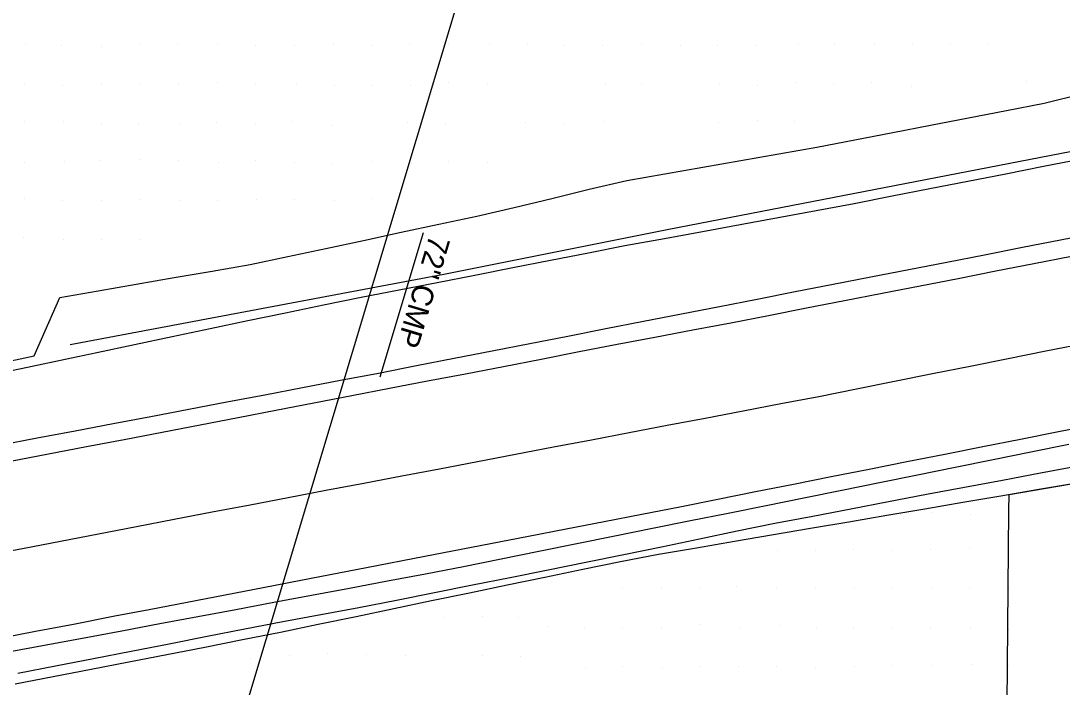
# Model space of a CAD drawing. Extents: x 2262025 to 2264532, y 740981 to 742724.
# Drawn here: x 2263020.8 to 2263155.7, y 742116.6 to 742202.9 of the extents above; entities that cross this region are included whole.
import ezdxf

# ---------------------------------------------------------------- set-up
doc = ezdxf.new("R2010")
doc.units = 0
for name, color, linetype in [('DR_X_Storm_Sewer', 7, 'Continuous'), ('DR_X_Text', 7, 'Continuous'), ('DT_X_Void', 7, 'Continuous'), ('GE_X_Alignment_1000_Curve_Data', 7, 'Continuous'), ('GE_X_Alignment_100_Cardinal_Points', 7, 'Continuous'), ('GE_X_Alignment_100_Curve_Data', 7, 'Continuous'), ('Ground Shots', 7, 'Continuous'), ('RW_X_CL_1000_Distances', 7, 'Continuous'), ('SC_Scratch2', 7, 'Continuous'), ('SV_X_Control_Cells_Found', 7, 'Continuous')]:
    doc.layers.add(name, color=color, linetype=linetype)

msp = doc.modelspace()

# ---------------------------------------------------------------- linework, layer by layer
at = {"layer": 'DR_X_Storm_Sewer'}
msp.add_line((2263148.87, 742443.51), (2262984.25, 741895.04), dxfattribs=at)
msp.add_line((2263148.87, 742443.51), (2262984.25, 741895.04), dxfattribs=at)
at = {"layer": 'DR_X_Text'}
msp.add_line((2263067.4, 742156.75), (2263073.01, 742175.44), dxfattribs=at)
msp.add_line((2263067.4, 742156.75), (2263073.01, 742175.44), dxfattribs=at)
at = {"layer": 'DT_X_Void'}
msp.add_lwpolyline([(2263148.35, 742084.34), (2263148.83, 742139.39), (2263148.85, 742141.53), (2263177.37, 742146.41), (2263223.67, 742154.36), (2263228.51, 742155.39), (2263234.29, 742156.62), (2263207.86, 742081.52), (2263207.2, 742079.17), (2263202.2, 742080.57), (2263196.1, 742079.91), (2263195.53, 742076.88), (2263158.09, 742069.91), (2263148.41, 742067.47)], close=True, dxfattribs=at)
at = {"layer": 'GE_X_Alignment_1000_Curve_Data'}
for points in [[(2263160.4, 742175.41), (2263155.5, 742174.46), (2263150.59, 742173.5), (2263145.68, 742172.54), (2263140.77, 742171.59), (2263135.87, 742170.63), (2263130.96, 742169.67), (2263126.05, 742168.71), (2263121.14, 742167.75), (2263116.24, 742166.79), (2263111.33, 742165.84), (2263106.42, 742164.88), (2263101.51, 742163.92), (2263096.61, 742162.96), (2263091.7, 742162), (2263086.79, 742161.04), (2263081.89, 742160.09), (2263076.98, 742159.13), (2263072.07, 742158.17), (2263067.16, 742157.21), (2263062.25, 742156.27), (2263057.34, 742155.33), (2263052.43, 742154.4), (2263047.52, 742153.47), (2263042.6, 742152.54), (2263037.69, 742151.6), (2263032.78, 742150.67), (2263027.87, 742149.74), (2263022.96, 742148.8), (2263018.04, 742147.87)], [(2263019.19, 742121.12), (2263024.11, 742122.04), (2263029.02, 742122.96), (2263033.94, 742123.88), (2263038.85, 742124.8), (2263043.77, 742125.72), (2263048.68, 742126.64), (2263053.6, 742127.56), (2263058.51, 742128.48), (2263063.42, 742129.4), (2263068.34, 742130.32), (2263073.25, 742131.24), (2263078.16, 742132.19), (2263083.06, 742133.18), (2263087.96, 742134.17), (2263092.87, 742135.16), (2263097.77, 742136.15), (2263102.67, 742137.14), (2263107.57, 742138.13), (2263112.47, 742139.12), (2263117.37, 742140.11), (2263122.27, 742141.1), (2263127.17, 742142.09), (2263132.07, 742143.08), (2263136.98, 742144.07), (2263141.88, 742145.06), (2263146.78, 742146.05), (2263151.68, 742147.04), (2263156.58, 742148.03)]]:
    msp.add_lwpolyline(points, dxfattribs=at)
at = {"layer": 'GE_X_Alignment_100_Cardinal_Points'}
msp.add_lwpolyline([(2263027.21, 742160.95), (2263075.62, 742170.07), (2263104.79, 742175.88), (2263164.82, 742187.5), (2263200.07, 742194.4)], dxfattribs=at)
at = {"layer": 'GE_X_Alignment_100_Curve_Data'}
for points in [[(2263015.99, 742156.86), (2263020.89, 742157.85), (2263027.38, 742159.22), (2263030.68, 742159.92), (2263035.57, 742160.95), (2263040.46, 742161.98), (2263045.36, 742163.01), (2263050.25, 742164.04), (2263055.14, 742165.07), (2263060.03, 742166.1), (2263064.94, 742167.07), (2263069.85, 742168.03), (2263074.75, 742168.99), (2263079.66, 742169.95), (2263084.57, 742170.91), (2263089.47, 742171.87), (2263094.38, 742172.83), (2263099.1, 742173.75), (2263104.21, 742174.69), (2263109.12, 742175.6), (2263114.04, 742176.5), (2263118.96, 742177.41), (2263123.87, 742178.32), (2263128.79, 742179.23), (2263133.7, 742180.19), (2263138.6, 742181.15), (2263143.51, 742182.11), (2263148.42, 742183.07), (2263153.33, 742184.03), (2263158.23, 742185)], [(2263157.82, 742145.18), (2263152.91, 742144.28), (2263147.99, 742143.35), (2263143.08, 742142.43), (2263138.16, 742141.5), (2263133.25, 742140.56), (2263128.34, 742139.62), (2263123.43, 742138.69), (2263118.52, 742137.75), (2263113.62, 742136.75), (2263108.73, 742135.73), (2263103.83, 742134.71), (2263098.94, 742133.69), (2263094.04, 742132.7), (2263089.13, 742131.72), (2263084.23, 742130.74), (2263079.33, 742129.76), (2263074.43, 742128.77), (2263069.52, 742127.79), (2263064.61, 742126.85), (2263059.7, 742125.94), (2263054.78, 742125.01), (2263049.87, 742124.06), (2263044.97, 742123.11), (2263040.06, 742122.14), (2263035.15, 742121.18), (2263030.25, 742120.23), (2263025.34, 742119.28), (2263020.43, 742118.33)]]:
    msp.add_lwpolyline(points, dxfattribs=at)
at = {"layer": 'Ground Shots'}
for p, q in [((2263021.38, 742199.81), (2263021.38, 742199.81)), ((2263026.11, 742199.66), (2263026.11, 742199.66)), ((2263031.31, 742199.57), (2263031.31, 742199.57)), ((2263036.27, 742199.75), (2263036.27, 742199.75)), ((2263041.19, 742199.78), (2263041.19, 742199.78)), ((2263046.34, 742199.76), (2263046.34, 742199.76)), ((2263051.21, 742199.65), (2263051.21, 742199.65)), ((2263056.27, 742199.74), (2263056.27, 742199.74)), ((2263061.37, 742199.76), (2263061.37, 742199.76)), ((2263066.26, 742199.7), (2263066.26, 742199.7)), ((2263071.19, 742199.87), (2263071.19, 742199.87)), ((2263076.24, 742199.77), (2263076.24, 742199.77)), ((2263081.59, 742199.89), (2263081.59, 742199.89)), ((2263086.43, 742199.86), (2263086.43, 742199.86)), ((2263091.27, 742199.7), (2263091.27, 742199.7)), ((2263096.24, 742199.63), (2263096.24, 742199.63)), ((2263101.24, 742199.8), (2263101.24, 742199.8)), ((2263106.3, 742199.74), (2263106.3, 742199.74)), ((2263111.11, 742199.7), (2263111.11, 742199.7)), ((2263116.12, 742199.69), (2263116.12, 742199.69)), ((2263121.52, 742199.75), (2263121.52, 742199.75)), ((2263126.19, 742199.79), (2263126.19, 742199.79)), ((2263131.36, 742199.77), (2263131.36, 742199.77)), ((2263136.29, 742199.86), (2263136.29, 742199.86)), ((2263141.32, 742199.76), (2263141.32, 742199.76)), ((2263146.2, 742199.87), (2263146.2, 742199.87)), ((2263076.19, 742194.85), (2263076.19, 742194.85)), ((2263131.05, 742194.86), (2263131.05, 742194.86)), ((2263151.1, 742194.97), (2263151.1, 742194.97)), ((2263021.34, 742194.62), (2263021.34, 742194.62)), ((2263026.29, 742194.47), (2263026.29, 742194.47)), ((2263031.28, 742194.61), (2263031.28, 742194.61)), ((2263036.34, 742194.75), (2263036.34, 742194.75)), ((2263041.28, 742194.68), (2263041.28, 742194.68)), ((2263046.35, 742194.82), (2263046.35, 742194.82)), ((2263051.29, 742194.68), (2263051.29, 742194.68)), ((2263056.54, 742194.77), (2263056.54, 742194.77)), ((2263061.42, 742194.56), (2263061.42, 742194.56)), ((2263066.36, 742194.53), (2263066.36, 742194.53)), ((2263071.37, 742194.54), (2263071.37, 742194.54)), ((2263081.32, 742194.81), (2263081.32, 742194.81)), ((2263096.63, 742194.69), (2263096.63, 742194.69)), ((2263101.29, 742194.76), (2263101.29, 742194.76)), ((2263111.33, 742194.77), (2263111.33, 742194.77)), ((2263116.24, 742194.55), (2263116.24, 742194.55)), ((2263121.21, 742194.82), (2263121.21, 742194.82)), ((2263126.16, 742194.75), (2263126.16, 742194.75)), ((2263136.2, 742194.41), (2263136.2, 742194.41)), ((2263021.36, 742189.85), (2263021.36, 742189.85)), ((2263026.36, 742189.79), (2263026.36, 742189.79)), ((2263031.33, 742189.56), (2263031.33, 742189.56)), ((2263036.04, 742189.54), (2263036.04, 742189.54)), ((2263041.33, 742189.54), (2263041.33, 742189.54)), ((2263046.16, 742189.72), (2263046.16, 742189.72)), ((2263051.29, 742189.56), (2263051.29, 742189.56)), ((2263056.04, 742189.89), (2263056.04, 742189.89)), ((2263070.97, 742189.72), (2263070.97, 742189.72)), ((2263086.26, 742189.7), (2263086.26, 742189.7)), ((2263091.28, 742189.63), (2263091.28, 742189.63)), ((2263096.32, 742189.86), (2263096.32, 742189.86)), ((2263111.17, 742189.72), (2263111.17, 742189.72)), ((2263116.24, 742189.9), (2263116.24, 742189.9)), ((2263121.09, 742189.81), (2263121.09, 742189.81)), ((2263061.1, 742189.29), (2263061.1, 742189.29)), ((2263075.86, 742189.45), (2263075.86, 742189.45)), ((2263021.33, 742184.51), (2263021.33, 742184.51)), ((2263026.45, 742184.7), (2263026.45, 742184.7)), ((2263031.21, 742184.77), (2263031.21, 742184.77)), ((2263036.17, 742184.86), (2263036.17, 742184.86)), ((2263041.32, 742184.82), (2263041.32, 742184.82)), ((2263046.38, 742184.52), (2263046.38, 742184.52)), ((2263051.2, 742184.83), (2263051.2, 742184.83)), ((2263056.28, 742184.53), (2263056.28, 742184.53)), ((2263061.19, 742184.43), (2263061.19, 742184.43)), ((2263066.32, 742184.69), (2263066.32, 742184.69)), ((2263071.42, 742184.39), (2263071.42, 742184.39)), ((2263076.3, 742184.63), (2263076.3, 742184.63)), ((2263081.27, 742184.47), (2263081.27, 742184.47)), ((2263021.28, 742179.8), (2263021.28, 742179.8)), ((2263026.29, 742179.55), (2263026.29, 742179.55)), ((2263031.3, 742179.56), (2263031.3, 742179.56)), ((2263036.35, 742179.77), (2263036.35, 742179.77)), ((2263041.4, 742179.62), (2263041.4, 742179.62)), ((2263046.27, 742179.59), (2263046.27, 742179.59)), ((2263051.33, 742179.67), (2263051.33, 742179.67)), ((2263056.27, 742179.77), (2263056.27, 742179.77)), ((2263061.42, 742179.66), (2263061.42, 742179.66)), ((2263066.26, 742179.82), (2263066.26, 742179.82)), ((2263021.21, 742174.81), (2263021.21, 742174.81)), ((2263026.31, 742174.49), (2263026.31, 742174.49)), ((2263031.34, 742174.53), (2263031.34, 742174.53)), ((2263036.32, 742174.61), (2263036.32, 742174.61)), ((2263138.74, 742139.13), (2263138.74, 742139.13)), ((2263143.86, 742138.97), (2263143.86, 742138.97)), ((2263148.83, 742139.39), (2263148.83, 742139.39)), ((2263118.84, 742134.22), (2263118.84, 742134.22)), ((2263123.78, 742134.31), (2263123.78, 742134.31)), ((2263128.75, 742134.45), (2263128.75, 742134.45)), ((2263133.76, 742134.32), (2263133.76, 742134.32)), ((2263138.7, 742134.43), (2263138.7, 742134.43)), ((2263143.67, 742134.48), (2263143.67, 742134.48)), ((2263148.77, 742134.26), (2263148.77, 742134.26)), ((2263098.79, 742129.31), (2263098.79, 742129.31)), ((2263103.8, 742129.28), (2263103.8, 742129.28)), ((2263108.8, 742129.4), (2263108.8, 742129.4)), ((2263113.53, 742129.56), (2263113.53, 742129.56)), ((2263118.77, 742129.3), (2263118.77, 742129.3)), ((2263123.77, 742129.37), (2263123.77, 742129.37)), ((2263128.8, 742129.37), (2263128.8, 742129.37)), ((2263133.81, 742129.3), (2263133.81, 742129.3)), ((2263138.81, 742129.37), (2263138.81, 742129.37)), ((2263143.79, 742129.34), (2263143.79, 742129.34)), ((2263148.82, 742129.38), (2263148.82, 742129.38)), ((2263075.63, 742125.63), (2263075.63, 742125.63)), ((2263080.6, 742125.7), (2263080.6, 742125.7)), ((2263085.28, 742125.65), (2263085.28, 742125.65)), ((2263089.01, 742124.4), (2263089.01, 742124.4)), ((2263093.85, 742124.33), (2263093.85, 742124.33)), ((2263098.83, 742124.3), (2263098.83, 742124.3)), ((2263103.8, 742124.34), (2263103.8, 742124.34)), ((2263108.74, 742124.64), (2263108.74, 742124.64)), ((2263114.04, 742124.19), (2263114.04, 742124.19)), ((2263119.12, 742124.52), (2263119.12, 742124.52)), ((2263123.89, 742124.14), (2263123.89, 742124.14)), ((2263128.75, 742124.11), (2263128.75, 742124.11)), ((2263133.77, 742124.32), (2263133.77, 742124.32)), ((2263138.73, 742124.31), (2263138.73, 742124.31)), ((2263143.9, 742124.2), (2263143.9, 742124.2)), ((2263148.84, 742124.09), (2263148.84, 742124.09)), ((2263055.63, 742120.68), (2263055.63, 742120.68)), ((2263060.59, 742120.98), (2263060.59, 742120.98)), ((2263065.62, 742120.78), (2263065.62, 742120.78)), ((2263080.64, 742120.73), (2263080.64, 742120.73)), ((2263050.65, 742120.28), (2263050.65, 742120.28)), ((2263070.69, 742120.62), (2263070.69, 742120.62)), ((2263085.55, 742120.55), (2263085.55, 742120.55)), ((2263133.73, 742119.33), (2263133.73, 742119.33)), ((2263138.83, 742119.33), (2263138.83, 742119.33)), ((2263144.11, 742119.49), (2263144.11, 742119.49)), ((2263148.76, 742119.4), (2263148.76, 742119.4)), ((2263094.01, 742119.14), (2263094.01, 742119.14)), ((2263098.77, 742119.26), (2263098.77, 742119.26)), ((2263103.99, 742119.09), (2263103.99, 742119.09)), ((2263108.81, 742119.29), (2263108.81, 742119.29)), ((2263113.82, 742119.2), (2263113.82, 742119.2)), ((2263118.7, 742119.27), (2263118.7, 742119.27)), ((2263123.83, 742119.09), (2263123.83, 742119.09)), ((2263128.82, 742119.27), (2263128.82, 742119.27))]:
    msp.add_line(p, q, dxfattribs=at)
at = {"layer": 'RW_X_CL_1000_Distances'}
for points in [[(2263019.51, 742145.84), (2263024.42, 742146.78), (2263029.33, 742147.72), (2263034.24, 742148.66), (2263039.15, 742149.61), (2263044.06, 742150.55), (2263048.97, 742151.49), (2263053.88, 742152.43), (2263058.79, 742153.38), (2263063.7, 742154.33), (2263068.61, 742155.28), (2263073.52, 742156.23), (2263078.43, 742157.17), (2263083.34, 742158.12), (2263088.25, 742159.07), (2263093.16, 742160.02), (2263098.07, 742160.97), (2263102.98, 742161.91), (2263107.89, 742162.84), (2263112.8, 742163.77), (2263117.71, 742164.72), (2263122.62, 742165.68), (2263127.52, 742166.64), (2263132.43, 742167.6), (2263137.34, 742168.55), (2263142.25, 742169.51), (2263147.15, 742170.47), (2263152.06, 742171.44), (2263156.96, 742172.41)], [(2263160.16, 742150.58), (2263155.25, 742149.62), (2263150.35, 742148.66), (2263145.44, 742147.69), (2263140.54, 742146.71), (2263135.63, 742145.74), (2263130.73, 742144.77), (2263125.82, 742143.79), (2263120.92, 742142.82), (2263116.02, 742141.85), (2263111.11, 742140.88), (2263106.21, 742139.9), (2263101.3, 742138.93), (2263096.4, 742137.96), (2263091.49, 742137.01), (2263086.58, 742136.07), (2263081.67, 742135.12), (2263076.76, 742134.17), (2263071.85, 742133.23), (2263066.94, 742132.28), (2263062.03, 742131.33), (2263057.12, 742130.39), (2263052.21, 742129.44), (2263047.3, 742128.49), (2263042.39, 742127.55), (2263037.48, 742126.6), (2263033.03, 742125.74), (2263027.66, 742124.7), (2263022.75, 742123.76), (2263017.84, 742122.81)]]:
    msp.add_lwpolyline(points, dxfattribs=at)
at = {"layer": 'SC_Scratch2'}
msp.add_lwpolyline([(2263158.53, 742161.05), (2263153.62, 742160.07), (2263148.72, 742159.09), (2263143.82, 742158.11), (2263138.92, 742157.13), (2263134.01, 742156.15), (2263129.11, 742155.17), (2263124.21, 742154.19), (2263119.3, 742153.25), (2263114.39, 742152.31), (2263109.47, 742151.38), (2263104.56, 742150.44), (2263099.65, 742149.5), (2263094.74, 742148.57), (2263089.83, 742147.63), (2263084.92, 742146.7), (2263080, 742145.76), (2263075.09, 742144.82), (2263070.18, 742143.89), (2263065.27, 742142.95), (2263060.36, 742142.02), (2263055.45, 742141.08), (2263050.53, 742140.15), (2263045.62, 742139.21), (2263040.71, 742138.27), (2263035.8, 742137.33), (2263030.89, 742136.39), (2263025.98, 742135.45), (2263021.07, 742134.5), (2263016.16, 742133.56)], dxfattribs=at)
at = {"layer": 'SV_X_Control_Cells_Found'}
for points in [[(2263017.68, 742158.46), (2263022.58, 742159.47), (2263025.91, 742167.05), (2263030.84, 742167.9), (2263035.77, 742168.76), (2263040.69, 742169.61), (2263045.62, 742170.46), (2263050.55, 742171.32), (2263055.44, 742172.34), (2263060.33, 742173.39), (2263065.22, 742174.43), (2263070.11, 742175.48), (2263075, 742176.52), (2263079.89, 742177.57), (2263084.76, 742178.68), (2263089.62, 742179.87), (2263094.48, 742181.05), (2263099.34, 742182.18), (2263104.27, 742183.05), (2263109.19, 742183.92), (2263114.12, 742184.79), (2263119.04, 742185.65), (2263123.97, 742186.52), (2263128.88, 742187.46), (2263133.79, 742188.41), (2263138.69, 742189.36), (2263143.6, 742190.3), (2263148.51, 742191.25), (2263153.42, 742192.21), (2263158.27, 742193.42)], [(2263020.11, 742117.01), (2263025.03, 742117.94), (2263029.93, 742118.89), (2263034.84, 742119.84), (2263039.75, 742120.79), (2263044.66, 742121.76), (2263049.56, 742122.73), (2263054.47, 742123.7), (2263059.36, 742124.71), (2263064.26, 742125.73), (2263069.15, 742126.75), (2263074.05, 742127.77), (2263078.94, 742128.79), (2263083.84, 742129.81), (2263088.73, 742130.83), (2263093.63, 742131.85), (2263098.52, 742132.86), (2263103.44, 742133.77), (2263108.37, 742134.61), (2263113.3, 742135.46), (2263123.15, 742137.14), (2263128.08, 742137.98), (2263133.01, 742138.83), (2263137.94, 742139.67), (2263142.87, 742140.51), (2263147.8, 742141.35), (2263152.73, 742142.2), (2263157.65, 742143.04)]]:
    msp.add_lwpolyline(points, dxfattribs=at)

# ---------------------------------------------------------------- texts
at = {"layer": 'DR_X_Text'}
msp.add_text('72" CMP', height=2.8, rotation=253.2931, dxfattribs=at).set_placement((2263073.81, 742175.27))
msp.add_text('72" CMP', height=2.8, rotation=253.2931, dxfattribs=at).set_placement((2263073.81, 742175.27))

doc.saveas('drawing.dxf')
